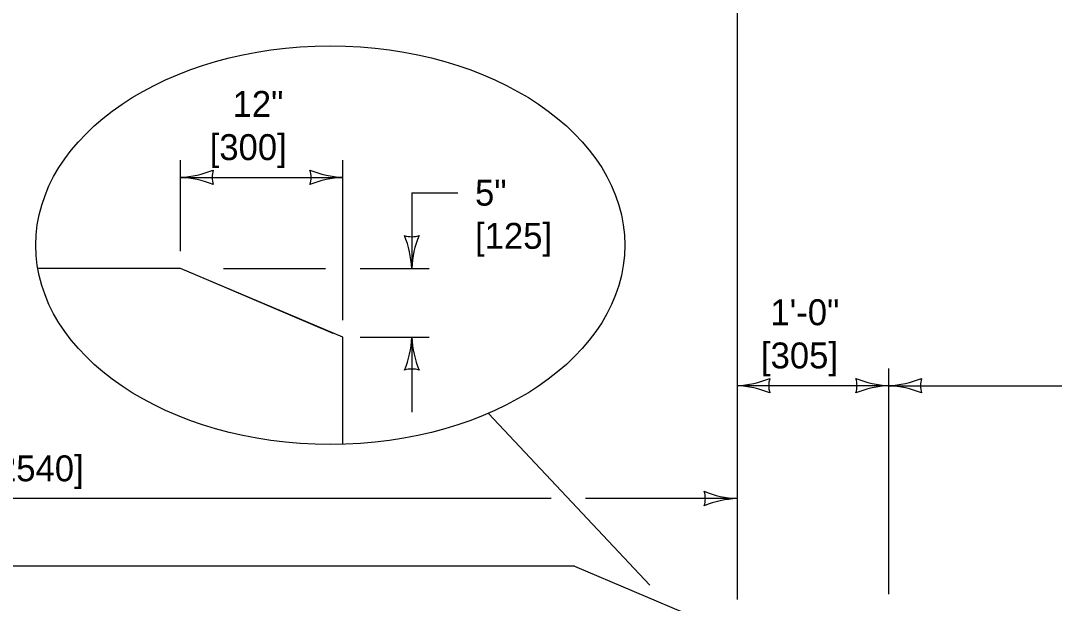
# Model space of a CAD drawing. Extents: x 49983 to 50021, y 49963.5 to 50011.4.
# Drawn here: x 50003.419 to 50005.814, y 49995.317 to 49996.667 of the extents above; entities that cross this region are included whole.
import ezdxf

# ---------------------------------------------------------------- set-up
doc = ezdxf.new("R2010")
doc.units = 0
for name, color, linetype in [('Level 1', 7, 'Continuous'), ('Level 2', 7, 'Continuous'), ('Level 3', 7, 'Continuous')]:
    doc.layers.add(name, color=color, linetype=linetype)

msp = doc.modelspace()

# ---------------------------------------------------------------- linework, layer by layer
at = {"layer": 'Level 1'}
for p, q in [((50003.7894, 49996.0931), (50003.4587, 49996.0931)), ((50004.1654, 49995.9335), (50003.7893, 49996.0931)), ((50003.8125, 49996.0833), (50004.1421, 49995.9434)), ((50004.1654, 49995.6857), (50004.1654, 49995.9335)), ((50004.7024, 49995.4035), (50000.7665, 49995.4035)), ((50004.7024, 49995.4035), (50004.9787, 49995.2862))]:
    msp.add_line(p, q, dxfattribs=at)
at = {"layer": 'Level 3'}
for p, q in [((50005.0789, 49997.0642), (50005.0789, 49995.3262)), ((50003.7893, 49996.1331), (50003.7893, 49996.344)), ((50004.1654, 49995.9735), (50004.1654, 49996.344)), ((50003.7893, 49996.304), (50004.1654, 49996.304)), ((50004.3253, 49996.2685), (50004.3253, 49996.0931)), ((50004.3253, 49996.2685), (50004.4319, 49996.2685)), ((50003.8893, 49996.0931), (50004.1254, 49996.0931)), ((50004.2054, 49996.0931), (50004.3653, 49996.0931)), ((50004.2054, 49995.9335), (50004.3653, 49995.9335)), ((50004.3253, 49995.9335), (50004.3253, 49995.7602)), ((50005.4304, 49995.3388), (50005.4304, 49995.8615)), ((50005.4304, 49995.8215), (50005.0789, 49995.8215)), ((50005.4304, 49995.8215), (50007.535, 49995.8215)), ((50004.877, 49995.3592), (50004.5027, 49995.7574)), ((50004.6482, 49995.56), (50002.1518, 49995.56)), ((50005.0789, 49995.56), (50004.7282, 49995.56))]:
    msp.add_line(p, q, dxfattribs=at)
for centre, radius, start, end in [((50003.7778, 49996.5367), 0.233, 272.8273, 292.0772), ((50003.7802, 49996.0819), 0.2223, 67.456, 87.6395), ((50003.9175, 49996.304), 0.0548, 162.1388, 197.8612), ((50004.1745, 49996.5261), 0.2223, 247.456, 267.6395), ((50004.0372, 49996.304), 0.0548, 342.1388, 17.8612), ((50004.1769, 49996.0713), 0.233, 92.8273, 112.0772), ((50004.3253, 49996.2213), 0.0548, 252.1388, 287.8612), ((50004.0925, 49996.0816), 0.233, 2.8273, 22.0772), ((50004.5474, 49996.084), 0.2223, 157.456, 177.6395), ((50004.1031, 49995.9427), 0.2223, 337.456, 357.6395), ((50004.558, 49995.945), 0.233, 182.8273, 202.0772), ((50004.3253, 49995.8053), 0.0548, 72.1388, 107.8612), ((50005.0674, 49996.0543), 0.233, 272.8273, 292.0772), ((50005.2071, 49995.8215), 0.0548, 162.1388, 197.8612), ((50005.4396, 49996.0437), 0.2223, 247.456, 267.6395), ((50005.3022, 49995.8215), 0.0548, 342.1388, 17.8612), ((50005.4189, 49996.0543), 0.233, 272.8273, 292.0772), ((50005.5586, 49995.8215), 0.0548, 162.1388, 197.8612), ((50005.0697, 49995.5994), 0.2223, 67.456, 87.6395), ((50005.4419, 49995.5888), 0.233, 92.8273, 112.0772), ((50005.4213, 49995.5994), 0.2223, 67.456, 87.6395), ((50005.0881, 49995.7822), 0.2223, 247.456, 267.6395), ((50004.9507, 49995.56), 0.0548, 342.1388, 17.8612), ((50005.0904, 49995.3273), 0.233, 92.8273, 112.0772)]:
    msp.add_arc(centre, radius, start, end, dxfattribs=at)
msp.add_ellipse((50004.1365, 49996.1469), major_axis=(0.6825, 0), ratio=0.676333, dxfattribs=at)

# ---------------------------------------------------------------- texts
at = {"layer": 'Level 2'}
for s, p in [('12"', (50003.9101, 49996.444)), ('[300]', (50003.8571, 49996.344)), ('5"', (50004.4719, 49996.2385)), ('[125]', (50004.4719, 49996.1385)), ('1\'-0"', (50005.1562, 49995.9615)), ('[305]', (50005.1344, 49995.8615)), ('8\'-4" [2540]', (50003.1599, 49995.6))]:
    msp.add_text(s, height=0.06, dxfattribs=at).set_placement(p)

doc.saveas('drawing.dxf')
